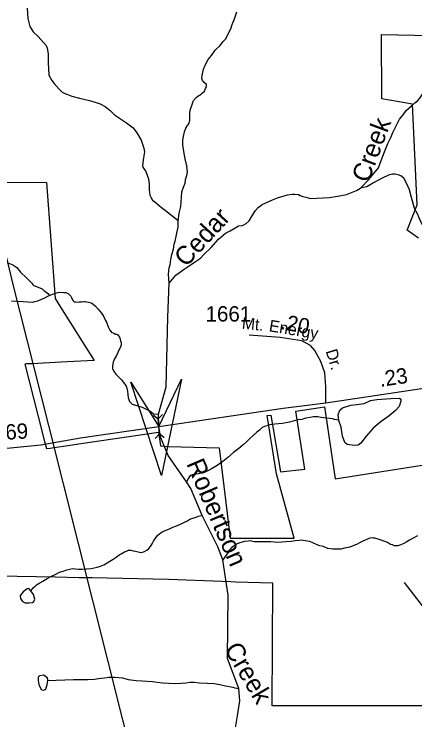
# Model space of a CAD drawing. Extents: x 2056842 to 2160602, y 826753 to 1016856.
# Drawn here: x 2098744 to 2102005, y 861080 to 866824 of the extents above; entities that cross this region are included whole.
import ezdxf

# ---------------------------------------------------------------- set-up
doc = ezdxf.new("R2010")
doc.units = 0
for name, color, linetype in [('Exist Boundary Political City Limit New', 7, 'Continuous'), ('Exist Hydrographic Creek Single Shore', 7, 'Continuous'), ('Exist Hydrographic Creek Single Shore Label', 7, 'Continuous'), ('Exist Hydrographic Misc Water Feature', 7, 'Continuous'), ('Exist Road Non-System Type 51', 7, 'Continuous'), ('Exist Road Primary NC Attributed', 7, 'Continuous'), ('Exist Road Primary NC Service Mileage Hundredths English Label', 7, 'Continuous'), ('Exist Road Secondary Mileage Hundredths English Label', 7, 'Continuous'), ('Exist Road Secondary Structure Culvert Attributed CELL', 7, 'Continuous'), ('Exist Road Secondary Structure Culvert CELL', 7, 'Continuous'), ('Exist Road Secondary Type 51 Attributed', 7, 'Continuous'), ('Exist Road Secondary Type 51 Label', 7, 'Continuous'), ('Exist Road Secondary Type 51 Number Label', 7, 'Continuous'), ('Exist Utilities Electrical Transmission Line', 7, 'Continuous'), ('Map Preparation Boundary City Limit Buffer Line', 7, 'Continuous')]:
    doc.layers.add(name, color=color, linetype=linetype)

msp = doc.modelspace()

# ---------------------------------------------------------------- linework, layer by layer
at = {"layer": 'Exist Boundary Political City Limit New'}
for points in [[(2102034, 865000), (2101940.8, 865066.2), (2102022, 865270.5), (2101986.5, 866090.4), (2101736.8, 866135), (2101734.2, 866658.4), (2102403.8, 866644.6)], [(2098558.5, 865455.9), (2099007, 865453.8), (2099076.8, 864509.5), (2099121.8, 864438.4), (2099396, 864004.3), (2099176, 863993.2), (2098887.5, 863978.6), (2098843.8, 863976.4), (2098831, 863975.8), (2098937, 863558.9), (2098991, 863346.8), (2099006, 863288.1), (2099037.5, 863291.9), (2099105.5, 863302.4), (2099125.5, 863305.4), (2099219.2, 863318.8), (2099252.5, 863323.6), (2099436.8, 863350.4), (2099918, 863422.2), (2099933.5, 863310.2), (2100000, 863305.8), (2100411.5, 863295), (2100501.5, 862557.6), (2101022.8, 862558.6), (2100878.8, 863081.4), (2100804, 863556.1), (2100833.8, 863560.6), (2100911.2, 863099.2), (2101108, 863120.5), (2101037.2, 863591.4), (2101234, 863621.2)], [(2101234, 863621.2), (2101269.2, 863626.5), (2101357.2, 863040.6), (2102201.5, 863173.7)], [(2100507.5, 862202.6), (2100000, 862221.8), (2099376.5, 862234.9), (2099273, 862237.1), (2099080.5, 862241.1), (2098609.5, 862249.8)], [(2102062.5, 861193.2), (2101980.2, 861193.4), (2101932, 861193.6), (2101887.2, 861193.6), (2101794.5, 861193.8), (2101709.5, 861194), (2101488.2, 861194), (2101481, 861194.5), (2101454.8, 861194.6), (2101329.5, 861194.9), (2101224.5, 861195.1), (2101153, 861195.2), (2100848, 861195.6), (2100844.2, 861195.6), (2100849, 862193.6), (2100545, 862201.1), (2100507.5, 862202.6)]]:
    msp.add_lwpolyline(points, dxfattribs=at)
at = {"layer": 'Exist Hydrographic Creek Single Shore'}
for points in [[(2098848.9, 866871.1), (2098854.9, 866787.2), (2098870.7, 866721.7), (2098899.9, 866679.2), (2098940, 866640.2), (2099003.2, 866567.3), (2099011.7, 866546.6), (2099021.5, 866501.6), (2099020.2, 866428.6), (2099026.1, 866325.4), (2099050.1, 866283.5), (2099070.4, 866259.4), (2099110.4, 866211.6), (2099132.1, 866191.6), (2099152.2, 866179.6), (2099172.1, 866171.8), (2099212.5, 866155.9), (2099276.3, 866138.2), (2099356.4, 866120.2), (2099412.4, 866104.4), (2099444.6, 866092.7), (2099484.6, 866070.8), (2099524.4, 866038.8), (2099560.9, 866002.8), (2099659.1, 865939.3), (2099711.2, 865897.7), (2099741.1, 865857.4), (2099777.4, 865797.6), (2099799.6, 865733.8), (2099803.5, 865701.9), (2099796.1, 865654), (2099788.3, 865591.9), (2099792.2, 865577.8), (2099796.1, 865570), (2099814.3, 865542.1), (2099826.6, 865513.8), (2099838.3, 865482), (2099842.4, 865438), (2099842.8, 865394.1), (2099848.6, 865350.2), (2099856.6, 865333.9), (2099870.9, 865308.3), (2099889, 865296.2), (2099923, 865266.3), (2099942.9, 865250.3), (2099975.1, 865226.4), (2100079.3, 865142.8)], [(2100079.2, 865142.6), (2100087, 865204.8), (2100098.9, 865256.7), (2100106.7, 865332.7), (2100108.6, 865376.6), (2100122.5, 865414.7), (2100134.4, 865448.9), (2100138.2, 865476.7), (2100150, 865509), (2100153.9, 865536.8), (2100147.8, 865588.7), (2100135.8, 865644.8), (2100123.3, 865706.7), (2100117.2, 865760.6), (2100115.3, 865796.8), (2100121.2, 865828.8), (2100128.9, 865864.7), (2100141, 865896.6), (2100154.9, 865916.7), (2100162.7, 865928.7), (2100166.8, 865936.8), (2100174.8, 865960.9), (2100172.4, 865988.8), (2100172.4, 866016.7), (2100176.5, 866040.9), (2100192.2, 866088.8), (2100204, 866120.8), (2100224.2, 866144.9), (2100239.9, 866157.1), (2100265.8, 866173), (2100277.8, 866183.2), (2100293.9, 866197.3), (2100299.9, 866219.2), (2100305.6, 866227.3), (2100309.8, 866239.3), (2100309.7, 866251.1), (2100289.7, 866267.3), (2100277.6, 866283), (2100271.4, 866301.1), (2100273.5, 866325), (2100283.4, 866375), (2100299.2, 866409.2), (2100323.2, 866455.3), (2100349.1, 866487.2), (2100380.8, 866529.5), (2100420.7, 866569.4), (2100442.6, 866597.5), (2100466.4, 866623.6), (2100486.3, 866663.8), (2100506.1, 866703.8), (2100518, 866740), (2100536, 866783.9), (2100555.9, 866841.9)], [(2101562.1, 865407.3), (2101629.8, 865477.4), (2101671.8, 865525.8), (2101707.6, 865573.6), (2101731.4, 865631.8), (2101757.2, 865703.8), (2101784.8, 865771.8), (2101808.8, 865819.9), (2101824.7, 865859.9), (2101848.7, 865908), (2101878.4, 865968.1), (2101908.4, 866004.2), (2101934, 866038.4), (2101975.8, 866076.6), (2102003.9, 866102.6), (2102025.9, 866118.6), (2102045.7, 866138.8), (2102065.7, 866170.9), (2102091.7, 866206.8), (2102109.6, 866231), (2102133.2, 866263)], [(2100004.3, 864633.6), (2100060.8, 864698.7), (2100126.5, 864748.9), (2100176.3, 864781), (2100220.2, 864809), (2100260.2, 864837.4), (2100290.1, 864871.2), (2100347.9, 864923.5), (2100405.8, 864991.8), (2100463.5, 865039.9), (2100501.4, 865060.1), (2100533.3, 865080.1), (2100569.4, 865100.3), (2100601.4, 865104.3), (2100631.2, 865120.4), (2100655.3, 865140.6), (2100674.9, 865172.6), (2100706.9, 865224.5), (2100730.7, 865250.6), (2100762.7, 865274.8), (2100792.5, 865289), (2100846.5, 865311.2), (2100886.5, 865327.1), (2100932.4, 865341.2), (2100968.4, 865353.3), (2101008.5, 865357.7), (2101028.6, 865359.6), (2101056.4, 865355.7), (2101072.3, 865347.9), (2101092.5, 865339.9), (2101116.6, 865333.8), (2101154.4, 865321.9), (2101308.5, 865330.5), (2101392.5, 865344.9), (2101448.5, 865356.8), (2101490.2, 865373), (2101528.2, 865387.3), (2101562.1, 865407.3)], [(2100004.3, 864633.6), (2099998.6, 864706.6), (2100002.5, 864734.4), (2100006.6, 864758.6), (2100012.3, 864782.4), (2100020.1, 864826.6), (2100028.2, 864866.4), (2100039.9, 864910.5), (2100046, 864950.7), (2100053.7, 864974.5), (2100061.7, 865014.7), (2100069.5, 865054.6), (2100077.4, 865090.5), (2100079.1, 865126.5), (2100079.2, 865142.6)], [(2098313.8, 865039.1), (2098354.2, 865005.3), (2098398, 864975.6), (2098472.5, 864929.8), (2098522.5, 864893.8), (2098580.3, 864846.1), (2098632.6, 864818.3), (2098678.3, 864804.5), (2098732.5, 864784.5), (2098767.1, 864762.7), (2098794.8, 864724.7), (2098847.3, 864675), (2098870.9, 864649.1), (2098887.1, 864633.3), (2098895.1, 864623.1)], [(2099919.6, 863568.7), (2099980, 863790.5), (2099995.2, 864357.9), (2100004.3, 864633.6)], [(2099032.9, 864534.4), (2099041.3, 864538.4), (2099063.4, 864546.5), (2099079.2, 864552.6), (2099099.1, 864558.9), (2099118.8, 864560.8), (2099147.1, 864558.9), (2099163.3, 864556.9), (2099171.1, 864554.9), (2099185, 864547.2), (2099191.2, 864540.9), (2099197.1, 864535.2), (2099205.1, 864527.1), (2099211.1, 864517.2), (2099219.1, 864499), (2099225, 864489.1), (2099233, 864483.1), (2099239.2, 864481.3), (2099247.2, 864479.3), (2099271.4, 864481.3), (2099291.2, 864483.2), (2099311.1, 864485.4), (2099323, 864485.6), (2099332.9, 864483.3), (2099349.3, 864479.6), (2099371.2, 864473.4), (2099383.5, 864465.5), (2099405.7, 864445.6), (2099427.6, 864421.6), (2099455.5, 864389.7), (2099471.5, 864364.1), (2099487.5, 864330), (2099495.9, 864315.9), (2099509.8, 864277.9), (2099523.8, 864251.9), (2099533.8, 864238.2), (2099541.8, 864232.2), (2099553.9, 864226.2), (2099567.9, 864220.1), (2099577.7, 864218.1), (2099587.7, 864212.2), (2099594.1, 864204.3), (2099600, 864194.2), (2099606.2, 864178.2), (2099609.9, 864164.2), (2099614, 864150.6), (2099616, 864142.2), (2099614.4, 864132.3), (2099608.5, 864114.1), (2099596.4, 864088.4), (2099588.4, 864070.5), (2099576.7, 864046.3), (2099560.5, 864018.3), (2099550.8, 863990.1), (2099544.9, 863962.2), (2099545.1, 863938.3), (2099552.7, 863920.1), (2099572.6, 863894.4), (2099593.1, 863872.1), (2099617.3, 863848.2), (2099633.1, 863826.4), (2099645.2, 863812.4), (2099655.4, 863796.6), (2099661.4, 863778.6), (2099665.3, 863754.5), (2099669.2, 863726.7), (2099671.4, 863704.5), (2099679.4, 863678.6), (2099683.7, 863670.6), (2099695.8, 863656.6), (2099703.8, 863650.5), (2099713.6, 863646.6), (2099723.7, 863642.6), (2099749.5, 863635.1), (2099765.9, 863631), (2099785.8, 863625.1), (2099807.8, 863614.9), (2099828.1, 863603.3), (2099841.8, 863597.1), (2099857.6, 863587), (2099877.9, 863571.3), (2099919.6, 863568.7)], [(2100442, 862383.2), (2100402.2, 862488.5), (2100274.3, 862744.4), (2100181, 862961.8), (2100145.5, 863017), (2099998, 863232.3), (2099938.6, 863374), (2099921, 863468.6), (2099919.6, 863568.7)], [(2100690.1, 860311), (2100682.1, 860386.7), (2100640.1, 860453.1), (2100623, 860627.4), (2100530.1, 860918), (2100562.1, 861112.9), (2100581.1, 861234.5), (2100572.6, 861335.8), (2100479.8, 861579.2), (2100485, 862093.7), (2100442, 862383.2)]]:
    msp.add_lwpolyline(points, dxfattribs=at)
at = {"layer": 'Exist Hydrographic Misc Water Feature'}
for points in [[(2102081.4, 865083.3), (2102055.1, 865127), (2102039.3, 865166.7), (2102024.6, 865199), (2102002.6, 865242.9), (2101976.6, 865330.9), (2101960.4, 865394.6), (2101936.2, 865446.5), (2101913.9, 865488.4), (2101889.7, 865508.3), (2101868.1, 865516.5), (2101843.9, 865520.1), (2101823.6, 865520.4), (2101790, 865512.1), (2101737.9, 865487.9), (2101668.2, 865449.8), (2101614.5, 865417.4), (2101562.2, 865407.5)], [(2098895.1, 864623.1), (2098899.2, 864617.2), (2098917.8, 864609.1), (2098938.3, 864601.6), (2098972.2, 864588), (2098988.6, 864572.1), (2099000.7, 864562.5), (2099017.3, 864550.2), (2099032.9, 864534.4)], [(2098721.6, 864489.5), (2098765.5, 864487.8), (2098817.6, 864483.9), (2098859.4, 864482.1), (2098895.1, 864480.3), (2098913.1, 864484), (2098937.1, 864490.2), (2098960.9, 864500.3), (2098993.1, 864514.6), (2099017.1, 864528.4), (2099032.9, 864534.4)], [(2101385.8, 863517.5), (2101380, 863563.6), (2101393.9, 863600.4), (2101416.7, 863619.4), (2101483.8, 863640.9), (2101533.2, 863647.3), (2101591.5, 863654.9), (2101642.1, 863678.9), (2101695.3, 863687.8), (2101809.2, 863695.4), (2101878.9, 863699.2), (2101890.3, 863690.3), (2101890.3, 863673.9), (2101876.4, 863630.8), (2101844.7, 863595.3), (2101794.1, 863553.5), (2101729.5, 863509.2), (2101664.9, 863453.4), (2101607.9, 863388.8), (2101566.1, 863331.8), (2101543.4, 863316.6), (2101513, 863312.8), (2101454.7, 863320.4), (2101435.7, 863338.1), (2101416.7, 863388.8), (2101405.3, 863462.3), (2101385.8, 863517.5)], [(2101385.8, 863517.5), (2101384, 863518), (2101351.8, 863523.7), (2101333.6, 863529.7), (2101309.6, 863533.8), (2101285.8, 863535.7), (2101264, 863537.5), (2101242.1, 863541.6), (2101216.1, 863545.5), (2101197.6, 863547.5), (2101177.7, 863545.3), (2101151.9, 863541), (2101117.8, 863535.2), (2101083.8, 863525), (2101051.6, 863520.9), (2101021.9, 863514.9), (2100984.2, 863502.7), (2100928, 863492.6), (2100894.1, 863490.4), (2100866.2, 863486.1), (2100822.2, 863480.2), (2100800, 863474.2), (2100780.3, 863467.9), (2100762.1, 863458.1), (2100744, 863441.7), (2100716.4, 863417.9), (2100690.1, 863393.9), (2100662.4, 863369.7), (2100634.5, 863343.5), (2100606.9, 863319.3), (2100572.4, 863289.2), (2100528.9, 863255.2), (2100482.8, 863215.1), (2100429.1, 863173), (2100383.1, 863143), (2100349.3, 863122.6), (2100313.4, 863104.4), (2100287.2, 863094.7), (2100265.4, 863086.6), (2100243.1, 863082.7), (2100209.5, 863076.4), (2100193.3, 863074.4), (2100181.4, 863068.5), (2100171.5, 863060.2), (2100161.5, 863046.4), (2100145.5, 863017)], [(2098879.5, 862130.9), (2098892.2, 862146.4), (2098900.4, 862156.5), (2098914.4, 862168.6), (2098926.5, 862178.5), (2098954.1, 862196.6), (2098976.3, 862208.7), (2098998, 862222.9), (2099012.2, 862230.9), (2099036.2, 862244.6), (2099084.1, 862267), (2099114.1, 862281.1), (2099142, 862291.1), (2099171.7, 862301.2), (2099194, 862307.2), (2099219.7, 862311.4), (2099239.8, 862309.5), (2099268.1, 862307.7), (2099297.8, 862307.7), (2099333.9, 862309.9), (2099372, 862311.9), (2099420, 862322), (2099445.9, 862331.9), (2099473.9, 862342.2), (2099501.6, 862358.3), (2099523.6, 862372.5), (2099549.6, 862388.4), (2099573.6, 862404.7), (2099599.4, 862422.6), (2099615.6, 862432.4), (2099641.3, 862446.7), (2099657.7, 862452.8), (2099675.1, 862460.6), (2099693.3, 862460.8), (2099713.6, 862456.9), (2099731.3, 862453), (2099753.6, 862447.1), (2099775.4, 862443), (2099789.3, 862445), (2099805.3, 862449.1), (2099823.6, 862461.4), (2099839.3, 862475.1), (2099853.1, 862491.3), (2099867.2, 862511.5), (2099877.1, 862535.6), (2099895.1, 862559.6), (2099913.2, 862583.3), (2099939, 862605.7), (2099952.9, 862613.7), (2099973, 862621.6), (2100006.9, 862635.7), (2100036.4, 862647.8), (2100064.9, 862660.1), (2100098.5, 862674), (2100130.5, 862689.9), (2100148.6, 862698.1), (2100172.6, 862712.3), (2100198.4, 862722.2), (2100226.1, 862730.6), (2100240.4, 862736.5), (2100268.1, 862742.5), (2100274.3, 862744.4)], [(2102026.6, 862577.8), (2101984.8, 862555.8), (2101960.8, 862542), (2101938.9, 862530), (2101914.9, 862515.7), (2101891.1, 862503.5), (2101865.1, 862497.7), (2101838.6, 862497.7), (2101822.6, 862503.3), (2101806.8, 862507.3), (2101781, 862523.4), (2101752.7, 862535.4), (2101728.9, 862543.1), (2101704.9, 862551.2), (2101678.9, 862559.2), (2101664.9, 862558.9), (2101652.8, 862560.7), (2101636.8, 862558.7), (2101624.7, 862552.7), (2101600.9, 862543), (2101581.1, 862534.7), (2101558.9, 862522.6), (2101530.8, 862508.5), (2101507, 862498.4), (2101475.3, 862486.6), (2101433.2, 862476.3), (2101403.3, 862469.9), (2101376.8, 862470.2), (2101336.8, 862469.8), (2101297.1, 862475.8), (2101261.2, 862489.8), (2101231, 862497.6), (2101208.9, 862505.3), (2101174.8, 862519.5), (2101148.8, 862531.6), (2101126.9, 862533.2), (2101111.1, 862537.2), (2101078.9, 862541.3), (2101062.7, 862540.9), (2101031.1, 862536.8), (2100996.9, 862532.7), (2100954.8, 862528.8), (2100888.8, 862524.7), (2100829.1, 862528.4), (2100772.9, 862528), (2100696.7, 862529.9), (2100665.1, 862535.9), (2100646.8, 862533.7), (2100615.1, 862531.7), (2100599.1, 862527.6), (2100581, 862521.4), (2100558.9, 862511.4), (2100543.3, 862501.6), (2100527.1, 862491.4), (2100511.1, 862477.3), (2100499, 862465.3), (2100491.6, 862451.4), (2100483.6, 862439.2), (2100442, 862383.2)], [(2098879.5, 862130.9), (2098863, 862148.6), (2098850.4, 862147.4), (2098817.4, 862120.8), (2098793.4, 862091.6), (2098794.6, 862068.8), (2098811.1, 862043.5), (2098832.6, 862033.3), (2098865.6, 862032.1), (2098893.4, 862034.6), (2098904.8, 862044.7), (2098912.4, 862063.7), (2098901, 862099.2), (2098879.5, 862130.9)], [(2099015, 861399.2), (2099009.9, 861365), (2098998.5, 861328.3), (2098982, 861318.2), (2098969.4, 861320.7), (2098950.4, 861356.2), (2098941.5, 861398), (2098941.5, 861429.7), (2098952.9, 861441.1), (2098983.3, 861446.1), (2098997.2, 861438.5), (2099012.4, 861424.6), (2099015, 861399.2)], [(2099015, 861399.2), (2099226.4, 861407.5), (2099260.5, 861407.7), (2099298.6, 861407.6), (2099342.9, 861409.8), (2099396.8, 861412.2), (2099430.7, 861416.4), (2099452.6, 861418.3), (2099480.5, 861422.2), (2099514.3, 861426.4), (2099560.7, 861426.7), (2099596.6, 861424.9), (2099626.7, 861422.8), (2099670.8, 861408.8), (2099736.8, 861399.2), (2099786.6, 861397.4), (2099868.9, 861391.4), (2099906.4, 861387.7), (2099952.7, 861381.9), (2100002.6, 861380), (2100058.3, 861376), (2100106.7, 861380.1), (2100144.9, 861382.4), (2100174.4, 861386.5), (2100208.4, 861386.6), (2100250.7, 861382.6), (2100316.9, 861379.1), (2100372.7, 861375.1), (2100416.8, 861369.2), (2100464.5, 861357.5), (2100496.5, 861351.4), (2100522.4, 861345.5), (2100540.4, 861341.5), (2100572.6, 861335.8)]]:
    msp.add_lwpolyline(points, dxfattribs=at)
at = {"layer": 'Exist Road Non-System Type 51'}
msp.add_lwpolyline([(2101918.5, 862197.4), (2102064.3, 862009.2), (2102072.3, 861999.5)], dxfattribs=at)
at = {"layer": 'Exist Road Primary NC Attributed'}
for points in [[(2101280.1, 863661.3), (2101516.8, 863694.6), (2102113.9, 863785), (2102624.9, 863868.1), (2102996.9, 863927.9)], [(2097232.7, 863339.7), (2097434.7, 863334), (2097843.8, 863302.8), (2098302.8, 863284.1), (2098715.1, 863293.4), (2098962.2, 863318.4), (2099284.2, 863374.5), (2099921, 863468.6), (2100933.2, 863615.6), (2101280.1, 863661.3)]]:
    msp.add_lwpolyline(points, dxfattribs=at)
at = {"layer": 'Exist Road Secondary Structure Culvert Attributed CELL'}
msp.add_lwpolyline([(2100107, 863852.3), (2099943.4, 863069.2), (2099693.5, 863829.2), (2099921, 863468.6)], close=True, dxfattribs=at)
at = {"layer": 'Exist Road Secondary Structure Culvert CELL'}
for p, q in [((2099877, 863560.9), (2099916.4, 863528.9)), ((2099950.5, 863566.5), (2099916.4, 863528.9)), ((2099925.7, 863408.3), (2099916.4, 863528.9)), ((2099891.6, 863370.7), (2099925.7, 863408.3)), ((2099965.1, 863376.3), (2099925.7, 863408.3))]:
    msp.add_line(p, q, dxfattribs=at)
at = {"layer": 'Exist Road Secondary Type 51 Attributed'}
msp.add_lwpolyline([(2101280.1, 863661.3), (2101281.1, 863791.2), (2101270.7, 863905.5), (2101239.6, 863997), (2101191.8, 864086.3), (2101154.4, 864125.8), (2101085.9, 864165.3), (2100907.3, 864192.3), (2100656, 864211)], dxfattribs=at)
at = {"layer": 'Exist Utilities Electrical Transmission Line'}
msp.add_lwpolyline([(2090208.9, 878090.6), (2090399.6, 877911.2), (2091042.2, 877021.2), (2091166.6, 876875.7), (2095091.8, 871822.6), (2095202.4, 871658.9), (2098164.4, 867008.7), (2098184.9, 866904.8), (2098734, 864623.2), (2099022.7, 863475.6), (2099626.1, 861080), (2100400.4, 858056.5), (2100951.6, 855844.8), (2101980.8, 853661.7), (2102801.4, 851906.3), (2103296.8, 850944.6), (2103702.1, 850075), (2103840.6, 849731.1), (2105377.5, 846510.3), (2106244.1, 844636.9), (2107548.3, 841869.9), (2108761.2, 839864.8), (2109358.7, 838871.2), (2109834.3, 838086.5)], dxfattribs=at)
at = {"layer": 'Map Preparation Boundary City Limit Buffer Line'}
for points in [[(2102034, 865000), (2101940.8, 865066.2), (2102022, 865270.5), (2101986.5, 866090.4), (2101736.8, 866135), (2101734.2, 866658.4), (2102403.8, 866644.6)], [(2098558.5, 865455.9), (2099007, 865453.8), (2099076.8, 864509.5), (2099121.8, 864438.4), (2099396, 864004.3), (2099176, 863993.2), (2098887.5, 863978.6), (2098843.8, 863976.4), (2098831, 863975.8), (2098937, 863558.9), (2098991, 863346.8), (2099006, 863288.1), (2099037.5, 863291.9), (2099105.5, 863302.4), (2099125.5, 863305.4), (2099219.2, 863318.8), (2099252.5, 863323.6), (2099436.8, 863350.4), (2099918, 863422.2), (2099933.5, 863310.2), (2100000, 863305.8), (2100411.5, 863295), (2100501.5, 862557.6), (2101022.8, 862558.6), (2100878.8, 863081.4), (2100804, 863556.1), (2100833.8, 863560.6), (2100911.2, 863099.2), (2101108, 863120.5), (2101037.2, 863591.4), (2101234, 863621.2)], [(2101234, 863621.2), (2101269.2, 863626.5), (2101357.2, 863040.6), (2102201.5, 863173.7)], [(2100507.5, 862202.6), (2100000, 862221.8), (2099376.5, 862234.9), (2099273, 862237.1), (2099080.5, 862241.1), (2098609.5, 862249.8)], [(2102062.5, 861193.2), (2101980.2, 861193.4), (2101932, 861193.6), (2101887.2, 861193.6), (2101794.5, 861193.8), (2101709.5, 861194), (2101488.2, 861194), (2101481, 861194.5), (2101454.8, 861194.6), (2101329.5, 861194.9), (2101224.5, 861195.1), (2101153, 861195.2), (2100848, 861195.6), (2100844.2, 861195.6), (2100849, 862193.6), (2100545, 862201.1), (2100507.5, 862202.6)]]:
    msp.add_lwpolyline(points, dxfattribs=at)

# ---------------------------------------------------------------- texts
at = {"layer": 'Exist Hydrographic Creek Single Shore Label'}
for s, rotation, p in [('Creek', 69.54692, (2101626.5, 865443.8)), ('Cedar', 47.61365, (2100142.4, 864757.6)), ('Robertson', 293.14175, (2100142.9, 863166.2)), ('Creek', 300.41119, (2100449, 861657.3))]:
    msp.add_text(s, height=150, rotation=rotation, dxfattribs=at).set_placement(p)
at = {"layer": 'Exist Road Primary NC Service Mileage Hundredths English Label'}
for s, rotation, p in [('.23', 8.60968, (2101723.9, 863789.1)), ('.69', 3.90343, (2098630, 863355.3))]:
    msp.add_text(s, height=125, rotation=rotation, dxfattribs=at).set_placement(p)
at = {"layer": 'Exist Road Secondary Mileage Hundredths English Label'}
msp.add_text('.20', height=125, rotation=349.14824, dxfattribs=at).set_placement((2100906.2, 864261.7))
at = {"layer": 'Exist Road Secondary Type 51 Label'}
for s, rotation, p in [('Mt.', 354.14084, (2100594, 864263.6)), ('Energy', 350.52239, (2100812.7, 864243.1)), ('Dr.', 286.81907, (2101277.8, 864081.3))]:
    msp.add_text(s, height=95, rotation=rotation, dxfattribs=at).set_placement(p)
at = {"layer": 'Exist Road Secondary Type 51 Number Label'}
msp.add_text('1661', height=125, dxfattribs=at).set_placement((2100301.3, 864321.8))

doc.saveas('drawing.dxf')
